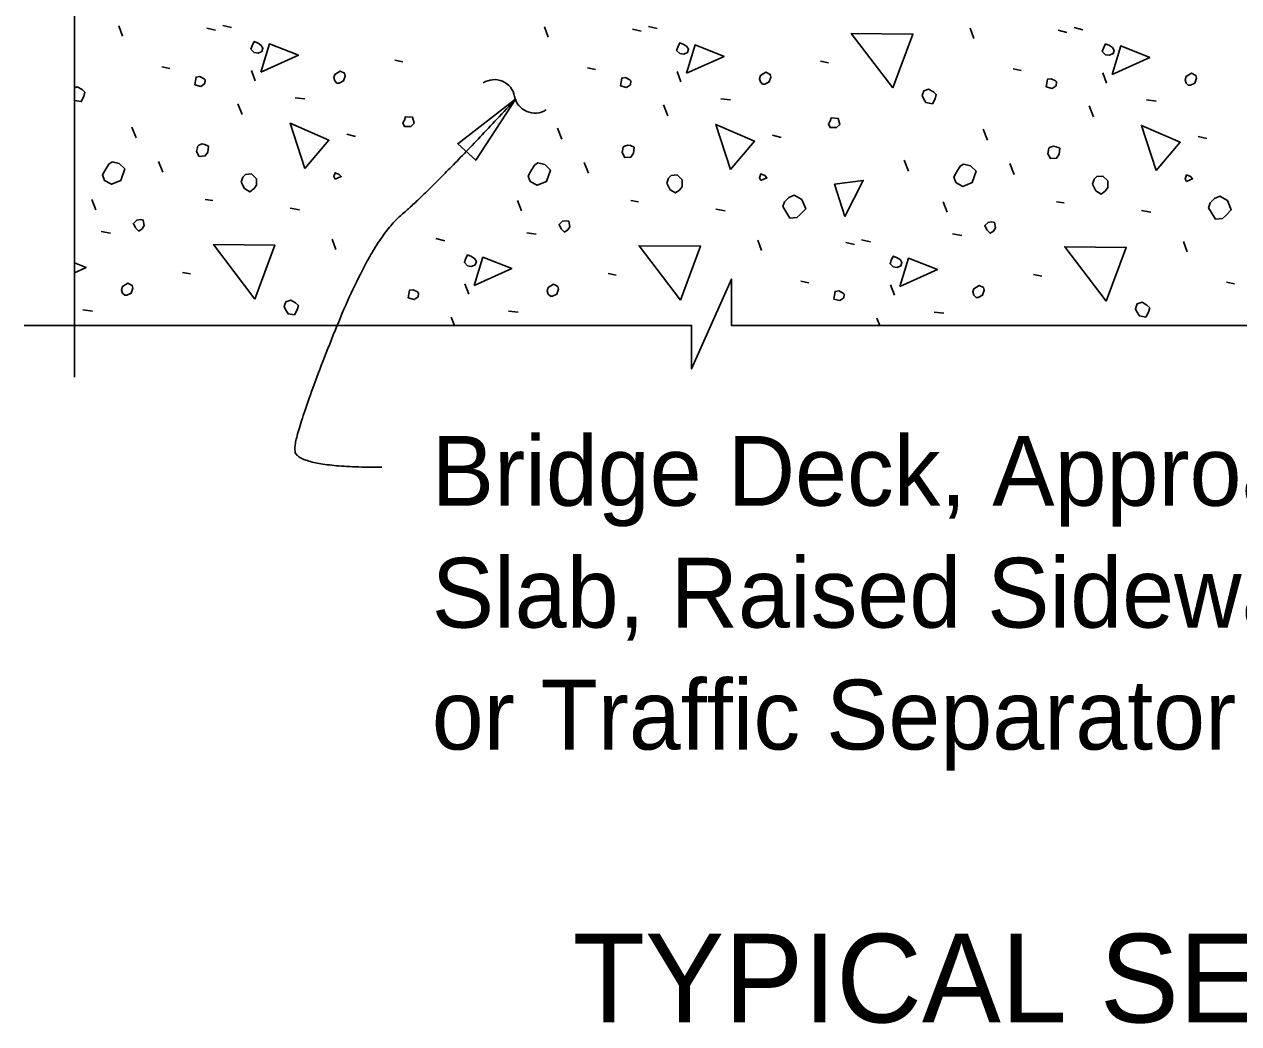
# Model space of a CAD drawing. Extents: x -7.9 to 27, y -3.1 to 14.6.
# Drawn here: x 1.988 to 3.302, y 1.985 to 3.068 of the extents above; entities that cross this region are included whole.
import ezdxf

# ---------------------------------------------------------------- set-up
doc = ezdxf.new("R2010")
doc.units = 0
for name, color, linetype in [('Border', 7, 'Continuous'), ('PlotBorder_dp', 7, 'Continuous'), ('TextMisc', 7, 'Continuous')]:
    doc.layers.add(name, color=color, linetype=linetype)

msp = doc.modelspace()

# ---------------------------------------------------------------- linework, layer by layer
at = {"layer": 'PlotBorder_dp'}
for points in [[(2.0419, 2.6856), (2.0419, 3.2068), (2.0923, 3.2068), (1.9948, 3.2499), (2.0419, 3.2499), (2.0419, 3.7593)], [(3.2257, 2.7414), (2.7531, 2.7414), (2.7531, 2.7916), (2.71, 2.6944), (2.71, 2.7414), (1.9876, 2.7414)], [(4.2194, 2.7414), (3.7696, 2.7414), (3.7696, 2.7916), (3.7265, 2.6944), (3.7265, 2.7414), (3.2257, 2.7414)]]:
    msp.add_lwpolyline(points, dxfattribs=at)
msp.add_lwpolyline([(2.5196, 2.9868), (2.4569, 2.9383), (2.4764, 2.9204)], close=True, dxfattribs=at)
for centre, start, end in [((2.4964, 2.9853), 10.958, 122.6852), ((2.5403, 2.9938), 190.958, 302.6852)]:
    msp.add_arc(centre, 0.0224, start, end, dxfattribs=at)
msp.add_open_spline([(2.3747, 2.5878), (2.2803, 2.5878), (2.2803, 2.6256), (2.3624, 2.8329), (2.4294, 2.8895), (2.5196, 2.9868)], degree=2, dxfattribs=at)
at = {"layer": 'TextMisc'}
for p, q in [((2.0939, 3.0547), (2.0898, 3.0659)), ((2.1853, 3.0635), (2.1947, 3.0611)), ((2.2024, 3.0664), (2.2118, 3.0641)), ((2.5547, 3.0535), (2.5506, 3.0647)), ((2.6632, 3.0653), (2.6726, 3.0629)), ((3.0155, 3.0523), (3.0114, 3.0635)), ((3.124, 3.0641), (3.1334, 3.0617)), ((2.6461, 3.0623), (2.6555, 3.06)), ((3.1069, 3.0611), (3.1163, 3.0588)), ((2.3886, 3.0287), (2.3974, 3.027)), ((2.8494, 3.0276), (2.8582, 3.0258)), ((2.1364, 3.0217), (2.1452, 3.0199)), ((2.2377, 3.0063), (2.2336, 3.0175)), ((2.5972, 3.0205), (2.606, 3.0187)), ((2.6985, 3.0052), (2.6944, 3.0164)), ((3.058, 3.0193), (3.0668, 3.0175)), ((3.1593, 3.004), (3.1552, 3.0152)), ((2.2807, 2.9881), (2.2913, 2.9869)), ((2.7415, 2.9869), (2.7521, 2.9857)), ((3.2023, 2.9857), (3.2129, 2.9845)), ((2.2236, 2.9698), (2.2189, 2.9816)), ((2.6844, 2.9686), (2.6797, 2.9804)), ((3.1452, 2.9674), (3.1405, 2.9792)), ((2.1087, 2.9445), (2.104, 2.9563)), ((2.3367, 2.9486), (2.3461, 2.9462)), ((2.5695, 2.9433), (2.5647, 2.9551)), ((2.7975, 2.9474), (2.8069, 2.9451)), ((3.0303, 2.9421), (3.0255, 2.9539)), ((3.2583, 2.9462), (3.2677, 2.9439)), ((2.1375, 2.9073), (2.1328, 2.9191)), ((2.9448, 2.9085), (2.9401, 2.9203)), ((2.5983, 2.9062), (2.5936, 2.918)), ((3.0591, 2.905), (3.0544, 2.9168)), ((2.0651, 2.8667), (2.0609, 2.8779)), ((2.1835, 2.8779), (2.1918, 2.8767)), ((2.2754, 2.8685), (2.2854, 2.8667)), ((2.5259, 2.8655), (2.5217, 2.8767)), ((2.6443, 2.8767), (2.6525, 2.8755)), ((2.7362, 2.8673), (2.7462, 2.8655)), ((2.9867, 2.8643), (2.9825, 2.8755)), ((3.1051, 2.8755), (3.1133, 2.8743)), ((3.197, 2.8661), (3.207, 2.8643)), ((2.071, 2.8431), (2.081, 2.8413)), ((2.5318, 2.8419), (2.5418, 2.8402)), ((2.9925, 2.8408), (3.0026, 2.839)), ((2.3249, 2.8237), (2.3208, 2.8349)), ((2.4333, 2.8355), (2.4428, 2.8331)), ((2.7857, 2.8225), (2.7816, 2.8337)), ((2.8771, 2.8313), (2.8865, 2.829)), ((2.8941, 2.8343), (2.9036, 2.8319)), ((3.2465, 2.8213), (3.2424, 2.8325)), ((2.1588, 2.7989), (2.1676, 2.7972)), ((2.6196, 2.7977), (2.6284, 2.796)), ((2.8281, 2.7895), (2.837, 2.7877)), ((3.0803, 2.7966), (3.0892, 2.7948)), ((3.2889, 2.7883), (3.2978, 2.7865)), ((2.4687, 2.7754), (2.4646, 2.7865)), ((2.9295, 2.7742), (2.9254, 2.7854)), ((2.0509, 2.7583), (2.0615, 2.7571)), ((2.4535, 2.7415), (2.4498, 2.7506)), ((2.5117, 2.7571), (2.5223, 2.7559)), ((2.9138, 2.7415), (2.9106, 2.7494)), ((2.9725, 2.7559), (2.9831, 2.7547))]:
    msp.add_line(p, q, dxfattribs=at)
for points in [[(2.9277, 2.9987), (2.8829, 3.0576), (2.9495, 3.057), (2.9277, 2.9987)], [(2.2365, 3.037), (2.2407, 3.0364), (2.2448, 3.0382), (2.246, 3.0417), (2.2442, 3.0446), (2.2407, 3.047), (2.2365, 3.0488), (2.2342, 3.0441), (2.233, 3.0405), (2.2365, 3.037)], [(2.2436, 3.0158), (2.253, 3.0464), (2.2843, 3.034), (2.2436, 3.0158)], [(2.6973, 3.0358), (2.7015, 3.0352), (2.7056, 3.037), (2.7068, 3.0405), (2.705, 3.0435), (2.7015, 3.0458), (2.6973, 3.0476), (2.695, 3.0429), (2.6938, 3.0393), (2.6973, 3.0358)], [(2.7044, 3.0146), (2.7138, 3.0452), (2.7451, 3.0329), (2.7044, 3.0146)], [(3.1581, 3.0346), (3.1623, 3.034), (3.1664, 3.0358), (3.1676, 3.0393), (3.1658, 3.0423), (3.1623, 3.0446), (3.1581, 3.0464), (3.1558, 3.0417), (3.1546, 3.0382), (3.1581, 3.0346)], [(3.1652, 3.0134), (3.1746, 3.0441), (3.2059, 3.0317), (3.1652, 3.0134)], [(2.1723, 3.0022), (2.1788, 3.0004), (2.1829, 3.0034), (2.1835, 3.0075), (2.1823, 3.0087), (2.1776, 3.0111), (2.1735, 3.0105), (2.1729, 3.0063), (2.1723, 3.0022)], [(2.3261, 3.004), (2.3285, 3.004), (2.3332, 3.0063), (2.3349, 3.0116), (2.3344, 3.0146), (2.3296, 3.0169), (2.3237, 3.0134), (2.3226, 3.0099), (2.3237, 3.0063), (2.3261, 3.004)], [(2.7869, 3.0028), (2.7893, 3.0028), (2.794, 3.0052), (2.7957, 3.0105), (2.7951, 3.0134), (2.7904, 3.0158), (2.7845, 3.0122), (2.7834, 3.0087), (2.7845, 3.0052), (2.7869, 3.0028)], [(3.2477, 3.0016), (3.2501, 3.0016), (3.2548, 3.004), (3.2565, 3.0093), (3.2559, 3.0122), (3.2512, 3.0146), (3.2453, 3.0111), (3.2442, 3.0075), (3.2453, 3.004), (3.2477, 3.0016)], [(2.0419, 2.9854), (2.0421, 2.9851), (2.0492, 2.9839), (2.0521, 2.9893), (2.0533, 2.994), (2.0503, 2.9969), (2.045, 2.9999), (2.0419, 2.9988)], [(2.6331, 3.001), (2.6396, 2.9993), (2.6437, 3.0022), (2.6443, 3.0063), (2.6431, 3.0075), (2.6384, 3.0099), (2.6343, 3.0093), (2.6337, 3.0052), (2.6331, 3.001)], [(2.9607, 2.9881), (2.9637, 2.9828), (2.9707, 2.9816), (2.9737, 2.9869), (2.9749, 2.9916), (2.9719, 2.9946), (2.9666, 2.9975), (2.9613, 2.9957), (2.9596, 2.9904), (2.9607, 2.9881)], [(3.0939, 2.9999), (3.1004, 2.9981), (3.1045, 3.001), (3.1051, 3.0052), (3.1039, 3.0063), (3.0992, 3.0087), (3.0951, 3.0081), (3.0945, 3.004), (3.0939, 2.9999)], [(2.2913, 2.9115), (2.2754, 2.9604), (2.3173, 2.9421), (2.2913, 2.9115)], [(2.3992, 2.9568), (2.4062, 2.9568), (2.4098, 2.9604), (2.408, 2.9669), (2.4003, 2.9674), (2.3992, 2.9639), (2.3974, 2.961), (2.3992, 2.9568), (2.398, 2.958)], [(2.7521, 2.9103), (2.7362, 2.9592), (2.7781, 2.9409), (2.7521, 2.9103)], [(2.86, 2.9557), (2.867, 2.9557), (2.8706, 2.9592), (2.8688, 2.9657), (2.8611, 2.9663), (2.86, 2.9627), (2.8582, 2.9598), (2.86, 2.9557), (2.8588, 2.9568)], [(3.2129, 2.9091), (3.197, 2.958), (3.2389, 2.9398), (3.2129, 2.9091)], [(2.1741, 2.9297), (2.177, 2.9244), (2.1835, 2.925), (2.1864, 2.9291), (2.187, 2.9356), (2.1829, 2.9374), (2.18, 2.938), (2.1764, 2.9368), (2.1753, 2.9356), (2.1741, 2.9297)], [(2.6349, 2.9286), (2.6378, 2.9233), (2.6443, 2.9238), (2.6472, 2.928), (2.6478, 2.9344), (2.6437, 2.9362), (2.6408, 2.9368), (2.6372, 2.9356), (2.636, 2.9344), (2.6349, 2.9286)], [(3.0957, 2.9274), (3.0986, 2.9221), (3.1051, 2.9227), (3.108, 2.9268), (3.1086, 2.9333), (3.1045, 2.935), (3.1016, 2.9356), (3.098, 2.9344), (3.0968, 2.9333), (3.0957, 2.9274)], [(2.0745, 2.8985), (2.0821, 2.8944), (2.0922, 2.8985), (2.0963, 2.9109), (2.0904, 2.9168), (2.0827, 2.9185), (2.0792, 2.9162), (2.0751, 2.9097), (2.0721, 2.9044), (2.0745, 2.8985)], [(2.2224, 2.8967), (2.2259, 2.8897), (2.2318, 2.8861), (2.2365, 2.8897), (2.2389, 2.8932), (2.2389, 2.9003), (2.2336, 2.9056), (2.2271, 2.905), (2.2242, 2.902), (2.2224, 2.8967)], [(2.3243, 2.8997), (2.3308, 2.9026), (2.3285, 2.905), (2.3243, 2.9068), (2.3226, 2.9026), (2.3243, 2.8997)], [(2.5353, 2.8973), (2.5429, 2.8932), (2.553, 2.8973), (2.5571, 2.9097), (2.5512, 2.9156), (2.5435, 2.9174), (2.54, 2.915), (2.5359, 2.9085), (2.5329, 2.9032), (2.5353, 2.8973)], [(2.7851, 2.8985), (2.7916, 2.9015), (2.7893, 2.9038), (2.7851, 2.9056), (2.7834, 2.9015), (2.7851, 2.8985)], [(2.9961, 2.8961), (3.0037, 2.892), (3.0138, 2.8961), (3.0179, 2.9085), (3.012, 2.9144), (3.0043, 2.9162), (3.0008, 2.9138), (2.9967, 2.9073), (2.9937, 2.902), (2.9961, 2.8961)], [(2.6832, 2.8956), (2.6867, 2.8885), (2.6926, 2.885), (2.6973, 2.8885), (2.6997, 2.892), (2.6997, 2.8991), (2.6944, 2.9044), (2.6879, 2.9038), (2.685, 2.9009), (2.6832, 2.8956)], [(2.8759, 2.8596), (2.8647, 2.8944), (2.8959, 2.8985), (2.8759, 2.8596)], [(3.144, 2.8944), (3.1475, 2.8873), (3.1534, 2.8838), (3.1581, 2.8873), (3.1605, 2.8908), (3.1605, 2.8979), (3.1552, 2.9032), (3.1487, 2.9026), (3.1458, 2.8997), (3.144, 2.8944)], [(3.2459, 2.8973), (3.2524, 2.9003), (3.2501, 2.9026), (3.2459, 2.9044), (3.2442, 2.9003), (3.2459, 2.8973)], [(2.8087, 2.8702), (2.8164, 2.8578), (2.824, 2.8584), (2.827, 2.8614), (2.8335, 2.8679), (2.8293, 2.8779), (2.8211, 2.8826), (2.8152, 2.8802), (2.8105, 2.8755), (2.8087, 2.8702)], [(3.2695, 2.869), (3.2772, 2.8567), (3.2848, 2.8573), (3.2878, 2.8602), (3.2942, 2.8667), (3.2901, 2.8767), (3.2819, 2.8814), (3.276, 2.8791), (3.2713, 2.8743), (3.2695, 2.869)], [(2.1081, 2.8472), (2.1116, 2.8437), (2.1151, 2.8461), (2.1175, 2.8496), (2.1163, 2.8555), (2.1134, 2.8561), (2.1093, 2.8555), (2.1057, 2.852), (2.1081, 2.8472)], [(2.5689, 2.8461), (2.5724, 2.8425), (2.5759, 2.8449), (2.5783, 2.8484), (2.5771, 2.8543), (2.5742, 2.8549), (2.5701, 2.8543), (2.5665, 2.8508), (2.5689, 2.8461)], [(3.0297, 2.8449), (3.0332, 2.8413), (3.0367, 2.8437), (3.0391, 2.8472), (3.0379, 2.8531), (3.035, 2.8537), (3.0309, 2.8531), (3.0273, 2.8496), (3.0297, 2.8449)], [(2.2371, 2.77), (2.1923, 2.829), (2.2589, 2.8284), (2.2371, 2.77)], [(2.6979, 2.7689), (2.6531, 2.8278), (2.7197, 2.8272), (2.6979, 2.7689)], [(3.1587, 2.7677), (3.1139, 2.8266), (3.1805, 2.826), (3.1587, 2.7677)], [(2.4675, 2.806), (2.4716, 2.8054), (2.4758, 2.8072), (2.477, 2.8107), (2.4752, 2.8137), (2.4716, 2.816), (2.4675, 2.8178), (2.4652, 2.8131), (2.464, 2.8095), (2.4675, 2.806)], [(2.4746, 2.7848), (2.484, 2.8154), (2.5153, 2.803), (2.4746, 2.7848)], [(2.9283, 2.8048), (2.9324, 2.8042), (2.9366, 2.806), (2.9377, 2.8095), (2.936, 2.8125), (2.9324, 2.8148), (2.9283, 2.8166), (2.926, 2.8119), (2.9248, 2.8083), (2.9283, 2.8048)], [(2.9354, 2.7836), (2.9448, 2.8142), (2.9761, 2.8019), (2.9354, 2.7836)], [(2.0419, 2.8092), (2.0545, 2.8042), (2.0419, 2.7986)], [(2.0963, 2.7742), (2.0986, 2.7742), (2.1034, 2.7765), (2.1051, 2.7818), (2.1045, 2.7848), (2.0998, 2.7871), (2.0939, 2.7836), (2.0928, 2.7801), (2.0939, 2.7765), (2.0963, 2.7742)], [(2.4033, 2.7712), (2.4098, 2.7695), (2.4139, 2.7724), (2.4145, 2.7765), (2.4133, 2.7777), (2.4086, 2.7801), (2.4045, 2.7795), (2.4039, 2.7754), (2.4033, 2.7712)], [(2.5571, 2.773), (2.5594, 2.773), (2.5642, 2.7754), (2.5659, 2.7807), (2.5653, 2.7836), (2.5606, 2.786), (2.5547, 2.7824), (2.5536, 2.7789), (2.5547, 2.7754), (2.5571, 2.773)], [(2.8641, 2.77), (2.8706, 2.7683), (2.8747, 2.7712), (2.8753, 2.7754), (2.8741, 2.7765), (2.8694, 2.7789), (2.8653, 2.7783), (2.8647, 2.7742), (2.8641, 2.77)], [(3.0179, 2.7718), (3.0202, 2.7718), (3.025, 2.7742), (3.0267, 2.7795), (3.0261, 2.7824), (3.0214, 2.7848), (3.0155, 2.7812), (3.0144, 2.7777), (3.0155, 2.7742), (3.0179, 2.7718)], [(2.2701, 2.7594), (2.2731, 2.7541), (2.2801, 2.753), (2.2831, 2.7583), (2.2843, 2.763), (2.2813, 2.7659), (2.276, 2.7689), (2.2707, 2.7671), (2.2689, 2.7618), (2.2701, 2.7594)], [(3.1917, 2.7571), (3.1947, 2.7518), (3.2017, 2.7506), (3.2047, 2.7559), (3.2059, 2.7606), (3.2029, 2.7636), (3.1976, 2.7665), (3.1923, 2.7647), (3.1905, 2.7594), (3.1917, 2.7571)]]:
    msp.add_lwpolyline(points, dxfattribs=at)

# ---------------------------------------------------------------- texts
at = {"layer": 'Border'}
msp.add_text('TYPICAL SECTION THRU JOINT', height=0.096, dxfattribs=at).set_placement((2.5812, 1.9866))
at = {"layer": 'PlotBorder_dp'}
for s, p in [('Bridge Deck, Approach ', (2.4287, 2.5462)), ('Slab, Raised Sidewalk', (2.4287, 2.4142)), ('or Traffic Separator', (2.4287, 2.2822))]:
    msp.add_text(s, height=0.0756, dxfattribs=at).set_placement(p)

doc.saveas('drawing.dxf')
